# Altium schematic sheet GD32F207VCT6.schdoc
size 127 x 101 mm
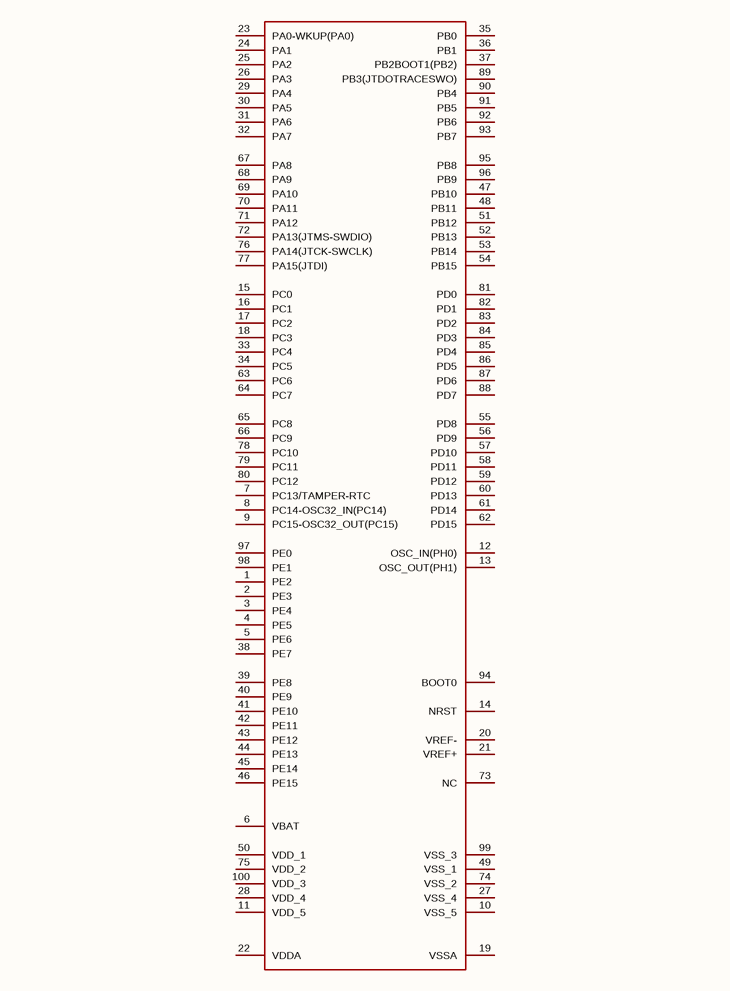
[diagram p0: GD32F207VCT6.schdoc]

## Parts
U?  gd32f207vct6  [LQFP-100_L14.0-W14.0-P0.50-LS16.0-BL]  (value not drawn)

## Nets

Not connected (* = marked no-connect by the designer): U? 1(PE2) 2(PE3) 3(PE4) 4(PE5) 5(PE6) 6(VBAT) 7(PC13/TAMPER-RTC) 8(PC14-OSC32_IN(PC14)) 9(PC15-OSC32_OUT(PC15)) 10(VSS_5) 11(VDD_5) 12(OSC_IN(PH0)) 13(OSC_OUT(PH1)) 14(NRST) 15(PC0) 16(PC1) 17(PC2) 18(PC3) 19(VSSA) 20(VREF-) 21(VREF+) 22(VDDA) 23(PA0-WKUP(PA0)) 24(PA1) 25(PA2) 26(PA3) 27(VSS_4) 28(VDD_4) 29(PA4) 30(PA5) 31(PA6) 32(PA7) 33(PC4) 34(PC5) 35(PB0) 36(PB1) 37(PB2BOOT1(PB2)) 38(PE7) 39(PE8) 40(PE9) 41(PE10) 42(PE11) 43(PE12) 44(PE13) 45(PE14) 46(PE15) 47(PB10) 48(PB11) 49(VSS_1) 50(VDD_1) 51(PB12) 52(PB13) 53(PB14) 54(PB15) 55(PD8) 56(PD9) 57(PD10) 58(PD11) 59(PD12) 60(PD13) 61(PD14) 62(PD15) 63(PC6) 64(PC7) 65(PC8) 66(PC9) 67(PA8) 68(PA9) 69(PA10) 70(PA11) 71(PA12) 72(PA13(JTMS-SWDIO)) 73(NC) 74(VSS_2) 75(VDD_2) 76(PA14(JTCK-SWCLK)) 77(PA15(JTDI)) 78(PC10) 79(PC11) 80(PC12) 81(PD0) 82(PD1) 83(PD2) 84(PD3) 85(PD4) 86(PD5) 87(PD6) 88(PD7) 89(PB3(JTDOTRACESWO)) 90(PB4) 91(PB5) 92(PB6) 93(PB7) 94(BOOT0) 95(PB8) 96(PB9) 97(PE0) 98(PE1) 99(VSS_3) 100(VDD_3)

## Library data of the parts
U? = gd32f207vct6: CPU内核:ARM Cortex-M3;CPU最大主频:120MHz;; Manufacturer: GigaDevice(兆易创新); AddInBom: yes; ModelId: 469e6cc70557486dbd01fd12ff814964; ModelName: LQFP-100_L14.0-W14.0-H1.4-LS16.0-P0.50; ModelTransform: 629.92,629.92,0,0,0,0,0,0,0; CPU Maximum Speed: 120MHz; Program Storage Size: 256KB; Program Memory Type: FLASH; Number of I/O: 82; ADC (Bit): 12bit; Voltage - Supply: 2.6V~3.6V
